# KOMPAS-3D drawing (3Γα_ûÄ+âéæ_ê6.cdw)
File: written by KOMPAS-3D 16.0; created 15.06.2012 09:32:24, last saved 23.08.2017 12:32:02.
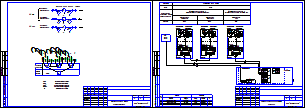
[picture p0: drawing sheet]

Sheets 1-2: A3, landscape

Title block, sheet 1: name: Руководство по эксплуатации; sheet number: 1; sheets: 27; organisation: ООО"Интелприбор"; sheet format: A3; stored path: W:\Users\smirnov_v\Desktop\шаблоны\4-х трубка\4-х трубка ГВС-max.cdw / D:\Проекты\Лыткарино\ул. Квартал 3А, д.25\710.74 РП.cdw; file name: 4-х трубка ГВС-max.cdw / 710.74 РП.cdw; cell 51: МО, Воскресенсикй р-н, п. Хорлово, ул. Интернациональная, д. 4; cell 320: Р
Title block, sheet 2: sheet number: 2

Views: Вид 2, Вид 3
Referenced files in C:\Program Files (x86)\ASCON\KOMPAS-3D V16\Sys\: spds.lcs, EngSys.lcs, GRAPHIC.LHS
Referenced files: graphic.tdp
Referenced files in W:\Users\smirnov_v\Desktop\шаблоны\4-х трубка\: 4-х трубка ГВС-max.cdw
Referenced files in D:\Проекты\Лыткарино\ул. Квартал 3А, д.25\: 710.74 РП.cdw
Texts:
  Смирнов В.С.
  УУ-3423
  GOST Common
  Normal
  List Paragraph
  heading 3
  для схемы
  txt
  Т0-элементы
  ВРУ
  Плата подключений
  СБ МКТС
  каб.
  Начало
  трассы
  Трассы
  Марка
  Проложен
  Изм. модуль (Т1)
  Изм. модуль (Т2)
  Изм. модуль (Т3)
  ВРУ 220В, 50 Гц
  ИМ (Т1)
  FTP
  ПВС
  Конец
  Кол-во и
  сеч. жил
  Длина,
  Преобразователь расхода
  Термопреобразователь
  Преобразователь давления
  Преобразователь цифровой
  Системный блок МКТС
  приборы
  по месту
  шкаф
  учета
  UQIES
  Подающий
  трубопровод
  Обратный
  УУГВС
  УУТЭ
  Функциональная схема
  Агрегат
  Системный блок  МКТС
  Среда
  Вода
  параметра и место
  отбора импульса
  Учет тепловой энергии и
  теплоносителя системы отопления
  отопления
  расхода горячей воды системы ГВС
  ГВС
  ИМ1
  ИМ2
  ИМ3
  UP+
  UP-
  ИМП
  Лин
  Измерительный
  модуль М121
  Pt 100
  Преобразователь
  температуры
  давления
  Размеры, параметризация
  сит. план
  подача ГВС
  обратка ГВС
  хвс
  обратка
  POLYLINE_STYLE_0.25_RGB_0_0_0
  стены
  Основная (не является границей для штриховки)
  POLYLINE_STYLE_0.18_RGB_0_0_0
  ХВС
  зеленая
  Красная тонкая
  арматура
  Подача
  Скрытая линия
  Ось Z
  Ось Y
  Ось X
  Образующая трубопровода (проектируемого)
  Трубопровод толщиной 0.6мм (одна линия)
  Трубопровод толщиной 1.2мм (одна линия)
  Трубопровод толщиной 1.0мм (одна линия)
  Трубопровод толщиной 0.8мм (одна линия)
  Трубопровод существующий (одна линия)
  Трубопровод невидимый (одна линия)
  Трубопровод демонтируемый (одна линия)
  Осевая трубопровода
  Осевая трубопровода (демонтируемого)
  Образующая трубопровода (существующего)
  Образующая трубопровода (невидимого)
  Изолированный трубопровод проектируемый (одна линия)
  Изолированный трубопровод существующий (одна линия)
  Образующая изоляции
  Изоляция
  Изолированный трубопровод невидимый (одна линия)
  Штрих пвс 075
  штрих пвс 2,5
  существующее оборудование
  Существующее оборудование
  K5LT_BASIC_RGB_0_0_255_THICK_0.53
  POLYLINE_STYLE_1.51_RGB_0_0_255
  POLYLINE_STYLE_0.50_RGB_128_128_128
  K5LT_AXLED_RGB_255_128_0_SC_1_THICK_0.18
  ACAD_ISO04W100_RGB_0_0_0_SC_1_THICK_0.18
  тонкая черная
  тонкая красная
  тонкая синяя
  тонкая оранж
  красн штрих
  пломбировка
  Провода
  синий штрих
  Стили документа
  G2co
  расход вторичной воды объемный
  расход вторичной воды объемный при 70гр
  Gco
  расход теплоносителя массовый
  расход теплоносит объемн подающ
  расход теплоносит объемн обр
  Лапир
  Ghvs
  Im1
  Im2
  Im3
  Im4
  Im5
  Khvs
  норматив ХВС
  число подъездов
  число этажей
  Nkv
  число квартир
  тепловая нагрузка на отопление
  сумма Q
  Qgvs
  тепловая нагрузка ГВС
  тепловая нагрузка на циркуляцию ГВС
  иммитовставка или под манометр
  ro1
  ro2
  ro3
  ro4
  верх предел темп граф
  нижн предел темп граф
  темп подачи ГВС
  темп обр ГВС
  темр хол воды
  vzdh
  Kchn
  Ktp
  Knp
  tnv
  Vклап
  KLP
  RPD
  RDS
  PUMP
  ro5
  beta
  tnv98
  Shifr
  Переход ГОСТ 17378-2001
  Переход
  ГОСТ
  Сталь 09Г2С ГОСТ 19281-89
  Втулка 20x50
  Лит-Масса-Масштаб
  Материал-Предприятие
  Title Specification
  Body Specification ( left align )
  Body Specificaton ( centered )
  Поз.
  Кол.
  Приме-
  чание
  Таблица спецификации
  Засыпка
  Штрих3
  Штрих2
  Штрих1
  Песок
  Штр0.5пр7
  Штр0.5пр12
  Штр0.3пр10
  Штр1.4пр21.21
  Штр1пр15
  Штр2.12пр35
  Штр1.5пр25
  Штр2.82пр42.42
  Штр2пр30
  SACNCR_ISO 1
  Электрощитовая
  Пр-1
  Ок-1
  Обозначение стандарта
  Типоразмер
  Пояснительная записка
  автоматизации
  Рабочие чертежи основного комплекта. ГОСТ Р 21.1101-2009 Ф3
  Стадия
  Лист
  Листов
  Изм.
  Кол.уч.
  №док.
  Подп.
  Дата
  Разраб.
  Пров.
  Т.контр.
  Н.контр.
  Утв.
  Изменение
  Номер документа
  Подпись
  Наименование объекта строительства, в состав которого входит здание, наим. микр
  Наименование здания (сооружения)
  Порядковый номер листа
  Количество листов в документе
  Наименование изображения
  Индекс предприятия, выпускающего документ
  Инв. № подл.
  Подп. и дата
  Взам. инв. №
  Инвентарный номер подлинника
  Подпись принявшего подлинник на хранение
  Инвентарный номер подлинника, взамен которого выпущен данный подлинник
  Согласовано
  Формат листа
  Согласование
  03 Рабочие чертежи основного комплекта. ГОСТ Р 21.1101-2009 Ф3
  Схема соединений внешних
  проводок
Dimensions and other numbers on the sheet: 220В; 50Гц; 1; 2; 3; 6; 5; 4; 2x2x0,52; 3х0,75; 20; 50; 13; 1,2,3; 4,5,6; 7,8,9; 10,11,12; 8; 10; 11; 7; 12; 0; 5,0; 3,2388; 0,0400; 40; 95; 3,1876; 4,5; 0,0; 0,0000; 70; 9; 4-20; 09Г2С; 27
